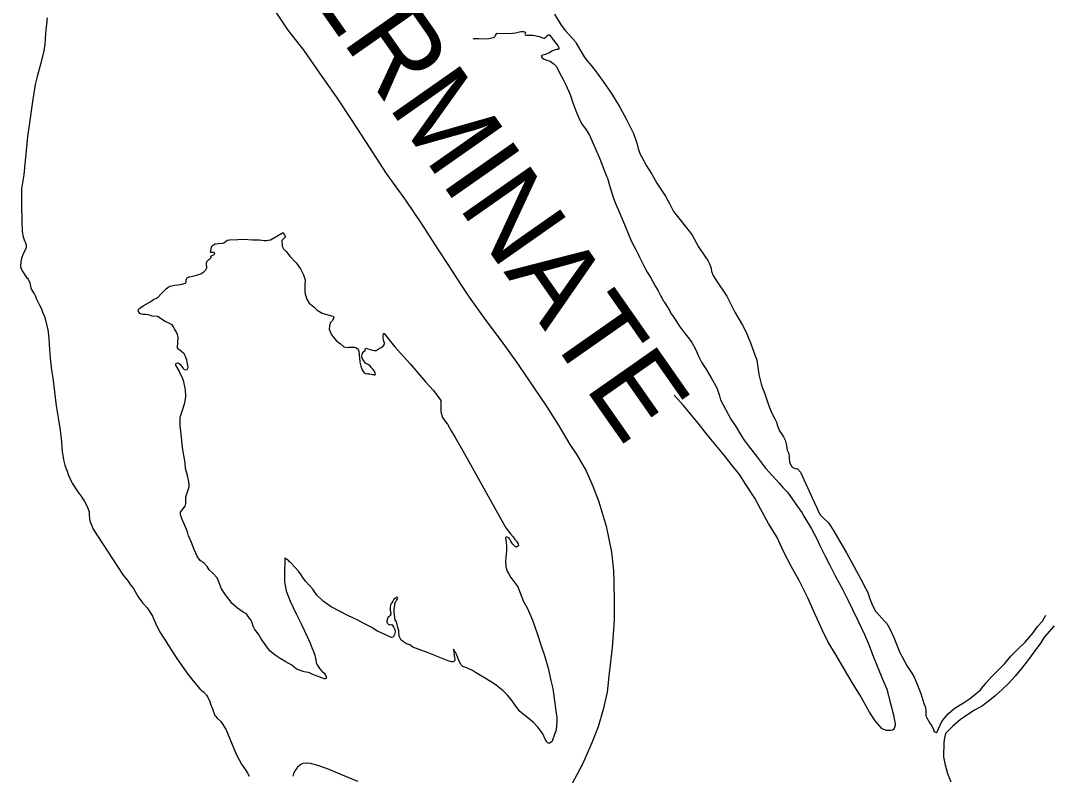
# Model space of a CAD drawing. Extents: x -117616 to 64730, y 54117 to 789866.
# Drawn here: x 62152 to 62218.2, y 55419.3 to 55467.6 of the extents above; entities that cross this region are included whole.
import ezdxf

# ---------------------------------------------------------------- set-up
doc = ezdxf.new("R2010")
doc.units = 0
doc.layers.add('3', color=7, linetype='Continuous')
doc.layers.add('9', color=7, linetype='Continuous')

msp = doc.modelspace()

# ---------------------------------------------------------------- linework, layer by layer
at = {"layer": '3'}
for points in [[(62167.221, 55469.914), (62169.146, 55467.026), (62170.158, 55465.72), (62171.155, 55464.273), (62172.226, 55462.748), (62173.278, 55461.172), (62174.343, 55459.546), (62175.44, 55457.841), (62176.668, 55456.141), (62177.687, 55454.634), (62178.711, 55453.027), (62179.456, 55451.891), (62180.181, 55450.764), (62180.743, 55449.943), (62181.823, 55448.438), (62182.805, 55447.141), (62183.875, 55445.626), (62184.872, 55444.188), (62185.722, 55442.926), (62186.49, 55441.71), (62187.187, 55440.512), (62187.643, 55439.857), (62188.244, 55438.826), (62188.664, 55437.837), (62189.021, 55436.897), (62189.271, 55436.143), (62189.515, 55435.279), (62189.688, 55434.452), (62189.861, 55433.615), (62189.977, 55432.454), (62190.018, 55431.652), (62190.026, 55430.457), (62190.023, 55429.271), (62189.911, 55427.528), (62189.707, 55425.883), (62189.584, 55424.672), (62189.328, 55423.557), (62189.002, 55422.449), (62188.593, 55421.428), (62187.997, 55420.048), (62186.777, 55417.77)], [(62173.609, 55418.938), (62172.642, 55419.361), (62171.787, 55419.72), (62171.25, 55419.909), (62170.915, 55420.017), (62170.592, 55420.094), (62170.321, 55420.124), (62170.102, 55420.095), (62169.964, 55420.039), (62169.761, 55419.861), (62169.6, 55419.653), (62169.498, 55419.448), (62169.454, 55419.286)]]:
    msp.add_lwpolyline(points, dxfattribs=at)
at = {"layer": '9'}
for points in [[(62186.218, 55468.042), (62186.646, 55467.346), (62186.911, 55466.974), (62187.193, 55466.674), (62187.549, 55466.266), (62187.592, 55466.198), (62187.838, 55465.785), (62188.117, 55465.314), (62188.213, 55465.157), (62188.579, 55464.74), (62188.875, 55464.359), (62189.319, 55463.734), (62189.86, 55462.972), (62190.395, 55462.089), (62190.825, 55461.312), (62191.271, 55460.405), (62191.405, 55460.049), (62191.508, 55459.721), (62191.569, 55459.453), (62191.682, 55459.135), (62191.779, 55458.938), (62192.103, 55458.348), (62192.434, 55457.809), (62192.767, 55457.239), (62193.31, 55456.397), (62193.579, 55455.935), (62193.839, 55455.413), (62194.998, 55453.942), (62195.429, 55453.155), (62195.885, 55452.5), (62196.034, 55452.275), (62196.153, 55452.038), (62196.234, 55451.77), (62196.272, 55451.571), (62196.371, 55451.323), (62196.533, 55451.038), (62197.233, 55450.011), (62197.764, 55448.987), (62198.247, 55448.152), (62198.453, 55447.749), (62198.752, 55447.017), (62198.953, 55446.482), (62199.156, 55445.908), (62199.25, 55445.308), (62199.292, 55444.999), (62199.436, 55444.392), (62199.504, 55444.183), (62199.659, 55443.808), (62199.932, 55442.984), (62200.065, 55442.658), (62200.229, 55442.293)], [(62153.722, 55467.814), (62153.622, 55466.815), (62153.569, 55466.12), (62153.525, 55465.706), (62153.327, 55464.915), (62153.08, 55464.061), (62152.96, 55463.554), (62152.76, 55462.3), (62152.607, 55461.099), (62152.463, 55460.209), (62152.24, 55457.759), (62152.094, 55456.879), (62152.077, 55455.793), (62152.106, 55454.81), (62152.123, 55454.137), (62152.186, 55453.798), (62152.254, 55453.6), (62152.298, 55453.501), (62152.341, 55453.412), (62152.364, 55453.353), (62152.387, 55453.284), (62152.392, 55453.143), (62152.357, 55453.031), (62152.199, 55452.703), (62152.091, 55452.408), (62152.038, 55452.225), (62152.031, 55451.893), (62152.067, 55451.754), (62152.175, 55451.557), (62152.399, 55451.204), (62152.461, 55451.157), (62152.503, 55451.088), (62152.612, 55450.861), (62152.685, 55450.532), (62152.741, 55450.384), (62152.806, 55450.276), (62152.858, 55450.218), (62152.921, 55450.14), (62152.976, 55450.011), (62153.032, 55449.853), (62153.217, 55449.478), (62153.359, 55449.193), (62153.427, 55448.984), (62153.548, 55448.698), (62153.761, 55447.862), (62153.833, 55447.313), (62153.86, 55446.882)], [(62180.997, 55466.46), (62181.069, 55466.483), (62181.339, 55466.483), (62181.93, 55466.476), (62182.207, 55466.538), (62182.317, 55466.552), (62182.356, 55466.564), (62182.395, 55466.605), (62182.413, 55466.646), (62182.441, 55466.708)], [(62182.441, 55466.708), (62182.46, 55466.728), (62182.498, 55466.78), (62182.546, 55466.822), (62183.057, 55466.802), (62183.516, 55466.82), (62183.705, 55466.858), (62183.883, 55466.905), (62184.062, 55466.932), (62184.131, 55466.945), (62184.232, 55466.939), (62184.313, 55466.912), (62184.344, 55466.873), (62184.327, 55466.802), (62184.319, 55466.762), (62184.33, 55466.722), (62184.391, 55466.704), (62184.641, 55466.694), (62184.821, 55466.701), (62185.033, 55466.669), (62185.255, 55466.608), (62185.387, 55466.553), (62185.468, 55466.526), (62185.529, 55466.518), (62185.589, 55466.52), (62185.598, 55466.531), (62185.676, 55466.574), (62185.743, 55466.667), (62185.791, 55466.709), (62185.801, 55466.72), (62185.89, 55466.733), (62186.05, 55466.488), (62186.376, 55466.089), (62186.439, 55466.001), (62186.484, 55465.883), (62186.487, 55465.812), (62186.447, 55465.801), (62186.418, 55465.79), (62186.328, 55465.776), (62186.219, 55465.752), (62186.081, 55465.706), (62185.857, 55465.556), (62185.768, 55465.523), (62185.63, 55465.467), (62185.551, 55465.454), (62185.452, 55465.42), (62185.403, 55465.398), (62185.355, 55465.356), (62185.419, 55465.248), (62185.542, 55465.162), (62185.715, 55465.099), (62185.937, 55465.037), (62186.185, 55464.846), (62186.341, 55464.691), (62186.537, 55464.287), (62186.742, 55463.914), (62186.937, 55463.529), (62187.212, 55462.897), (62187.373, 55462.381), (62187.627, 55461.758), (62187.858, 55461.225), (62187.978, 55460.989), (62188.199, 55460.716), (62188.423, 55460.353), (62188.84, 55459.425), (62189.105, 55458.783), (62189.283, 55458.337), (62189.549, 55457.675), (62189.594, 55457.546), (62189.755, 55457.02), (62189.917, 55456.454), (62190.074, 55456.028), (62190.415, 55455.258), (62190.57, 55454.882), (62190.681, 55454.595), (62190.968, 55453.913), (62191.166, 55453.459), (62191.425, 55452.977), (62191.557, 55452.69), (62191.654, 55452.493), (62191.937, 55451.932), (62192.153, 55451.528), (62192.367, 55451.175), (62192.678, 55450.625), (62192.85, 55450.34), (62193.023, 55450.006), (62193.056, 55449.927)], [(62162.142, 55446.606), (62162.069, 55446.693), (62162.104, 55447.066), (62162.123, 55447.349), (62162.075, 55447.558), (62161.999, 55447.705), (62161.881, 55447.912), (62161.794, 55448.069), (62161.721, 55448.157), (62161.435, 55448.316), (62161.292, 55448.371), (62160.79, 55448.692), (62160.458, 55448.72), (62160.337, 55448.755), (62160.185, 55448.799), (62160.014, 55448.833), (62159.864, 55448.837), (62159.743, 55448.842), (62159.651, 55448.899), (62159.555, 55449.056), (62159.581, 55449.147), (62159.668, 55449.241), (62159.872, 55449.39), (62160.361, 55449.67), (62160.546, 55449.798), (62160.811, 55449.909), (62161.012, 55450.138), (62161.244, 55450.358), (62161.35, 55450.463), (62161.485, 55450.569), (62161.593, 55450.643), (62161.91, 55450.696), (62162.099, 55450.723), (62162.347, 55450.773), (62162.585, 55450.833), (62162.632, 55450.915), (62162.628, 55451.016), (62162.655, 55451.097), (62162.692, 55451.179), (62162.809, 55451.244), (62163.058, 55451.274), (62163.365, 55451.356), (62163.562, 55451.424), (62163.757, 55451.552), (62163.882, 55451.678), (62163.946, 55451.821), (62163.954, 55451.892), (62163.919, 55452.011), (62163.924, 55452.132), (62163.98, 55452.234), (62164.085, 55452.349), (62164.134, 55452.391), (62164.192, 55452.434), (62164.221, 55452.465), (62164.217, 55452.565), (62164.452, 55452.695), (62164.418, 55452.804), (62164.188, 55452.795), (62164.204, 55452.896), (62164.219, 55453.007), (62164.255, 55453.129), (62164.302, 55453.202), (62164.369, 55453.285), (62164.476, 55453.359), (62164.944, 55453.398), (62165.043, 55453.422), (62165.257, 55453.581), (62165.406, 55453.607), (62165.935, 55453.638), (62166.324, 55453.653), (62166.886, 55453.605), (62167.326, 55453.602), (62167.618, 55453.554), (62167.768, 55453.559), (62167.847, 55453.583), (62167.907, 55453.595), (62168.026, 55453.61), (62168.838, 55454.074), (62168.989, 55453.799), (62168.748, 55453.568), (62168.753, 55453.448), (62168.766, 55453.378), (62168.782, 55453.208), (62168.849, 55453.039), (62169.026, 55452.856), (62169.268, 55452.554), (62169.675, 55452.138), (62169.95, 55451.757), (62170.145, 55451.363), (62170.238, 55451.055), (62170.23, 55450.753), (62170.216, 55450.602), (62170.217, 55450.311), (62170.244, 55450.131), (62170.357, 55449.814), (62170.507, 55449.548), (62170.828, 55449.29), (62171.025, 55449.107), (62171.343, 55448.908), (62171.545, 55448.846), (62171.778, 55448.775)], [(62193.228, 55449.632), (62193.056, 55449.927)], [(62193.228, 55449.632), (62193.399, 55449.357), (62193.591, 55449.053), (62193.645, 55448.945), (62193.815, 55448.701), (62194.017, 55448.387), (62194.188, 55448.103), (62194.642, 55447.508), (62194.779, 55447.342), (62195.011, 55447.04), (62195.206, 55446.656), (62195.447, 55446.123), (62195.63, 55445.788), (62195.94, 55445.278), (62196.25, 55444.778), (62196.596, 55444.139), (62196.766, 55443.633), (62196.836, 55443.365), (62197.495, 55442.125), (62197.824, 55441.655), (62198.166, 55441.096), (62198.358, 55440.792), (62198.675, 55440.363), (62198.928, 55440.031), (62199.213, 55439.671), (62199.656, 55439.075), (62199.74, 55438.978), (62200.148, 55438.532), (62200.588, 55438.037), (62200.828, 55437.765), (62201.121, 55437.455), (62201.777, 55436.537), (62202.052, 55436.166), (62202.182, 55435.92), (62202.664, 55435.115), (62202.999, 55434.465), (62203.196, 55434.041), (62203.543, 55433.361), (62203.836, 55432.79), (62204.183, 55432.101), (62204.647, 55431.245), (62205.005, 55430.536), (62205.288, 55429.944), (62205.669, 55429.166), (62206.062, 55428.347), (62206.305, 55427.754), (62206.617, 55426.962), (62206.883, 55426.29), (62207.215, 55425.499), (62207.48, 55424.857), (62207.596, 55424.459), (62207.68, 55424.091), (62207.809, 55423.624), (62207.857, 55423.425), (62207.929, 55423.126), (62207.941, 55423.066), (62208.028, 55422.638), (62208.022, 55422.527), (62207.96, 55422.334), (62207.912, 55422.282), (62207.854, 55422.239), (62207.745, 55422.205), (62207.475, 55422.214), (62207.18, 55422.323), (62206.75, 55422.838), (62206.388, 55423.377), (62205.754, 55424.487), (62205.273, 55425.282), (62204.78, 55426.106), (62204.233, 55427.039), (62203.741, 55427.854), (62203.371, 55428.613), (62202.803, 55429.826), (62202.428, 55430.705), (62201.865, 55431.798), (62201.39, 55432.674), (62200.892, 55433.618), (62200.465, 55434.556), (62199.92, 55435.449), (62199.392, 55436.392), (62199.036, 55437.072), (62198.451, 55437.953), (62198.056, 55438.58), (62197.529, 55439.243), (62197.077, 55439.817), (62196.331, 55440.722), (62196.225, 55440.859), (62195.848, 55441.306), (62195.415, 55441.872), (62194.984, 55442.397), (62194.47, 55443), (62193.861, 55443.674)], [(62171.778, 55448.775), (62171.909, 55448.75), (62172.03, 55448.724), (62172.052, 55448.685), (62172.074, 55448.616), (62171.982, 55448.431), (62171.877, 55448.306), (62171.794, 55448.112), (62171.783, 55447.891), (62171.938, 55447.525), (62172.032, 55447.408), (62172.232, 55447.155), (62172.511, 55446.945), (62172.728, 55446.763), (62172.859, 55446.738), (62172.999, 55446.723), (62173.049, 55446.735), (62173.329, 55446.736), (62173.409, 55446.739), (62173.5, 55446.713), (62173.634, 55446.608), (62173.68, 55446.469), (62173.726, 55446.059), (62173.747, 55445.768), (62173.807, 55445.519), (62173.874, 55445.341), (62173.918, 55445.242), (62174.034, 55445.106), (62174.115, 55445.059), (62174.176, 55445.052), (62174.276, 55445.036), (62174.377, 55445.029), (62174.467, 55445.013), (62174.558, 55444.996), (62174.618, 55444.989), (62174.659, 55444.97), (62174.699, 55444.962), (62174.739, 55444.983), (62174.725, 55445.073), (62174.69, 55445.203), (62174.596, 55445.309), (62174.501, 55445.426), (62174.407, 55445.533), (62174.334, 55445.59), (62174.232, 55445.647), (62174.14, 55445.693), (62174.057, 55445.78), (62173.994, 55445.858), (62173.897, 55446.025), (62173.886, 55446.065), (62173.881, 55446.175), (62173.887, 55446.276), (62173.896, 55446.296), (62173.942, 55446.409), (62173.981, 55446.43), (62174.058, 55446.504), (62174.103, 55446.626), (62174.152, 55446.668), (62174.264, 55446.622), (62174.557, 55446.544), (62174.657, 55446.527), (62174.797, 55446.533), (62174.856, 55446.575), (62174.993, 55446.651), (62175.11, 55446.716), (62175.246, 55446.812), (62175.323, 55446.905), (62175.312, 55446.915), (62175.329, 55446.996), (62175.284, 55447.115), (62175.26, 55447.224), (62175.246, 55447.324), (62175.235, 55447.344), (62175.23, 55447.474), (62175.265, 55447.606), (62175.294, 55447.618), (62175.958, 55446.77), (62176.962, 55445.674), (62177.948, 55444.517), (62178.47, 55443.955)], [(62153.86, 55446.882), (62153.924, 55446.03), (62154.014, 55445.26), (62154.084, 55444.76), (62154.199, 55443.881), (62154.304, 55442.981), (62154.46, 55442.083), (62154.566, 55441.434), (62154.628, 55440.874), (62154.645, 55440.684), (62154.689, 55440.072), (62154.771, 55439.533), (62154.795, 55439.434), (62154.865, 55439.185), (62154.944, 55438.947), (62155, 55438.799), (62155.068, 55438.6), (62155.277, 55438.126), (62155.32, 55438.038), (62155.692, 55437.49), (62155.956, 55437.138), (62156.117, 55436.854), (62156.299, 55436.549), (62156.39, 55436.272), (62156.413, 55436.202), (62156.42, 55436.032), (62156.441, 55435.731), (62156.466, 55435.621), (62156.677, 55435.097), (62158.231, 55432.707), (62158.604, 55432.139), (62158.909, 55431.759), (62159.047, 55431.554), (62159.248, 55431.291), (62159.558, 55430.77), (62159.791, 55430.448), (62159.845, 55430.35), (62160.137, 55430.05), (62160.297, 55429.805), (62160.468, 55429.52), (62160.721, 55428.938), (62160.807, 55428.78), (62160.926, 55428.544), (62161.246, 55428.054), (62161.492, 55427.642), (62161.641, 55427.417), (62161.982, 55426.888), (62162.322, 55426.399), (62162.661, 55425.9), (62163.061, 55425.413), (62163.512, 55424.868), (62163.523, 55424.859), (62163.74, 55424.676), (62163.928, 55424.463), (62164.002, 55424.365), (62164.122, 55424.129), (62164.213, 55423.841), (62164.303, 55423.593), (62164.47, 55423.168), (62164.502, 55423.119), (62164.606, 55423.003), (62164.855, 55422.791), (62165.174, 55422.302), (62165.828, 55420.7), (62166.163, 55420.06), (62166.46, 55419.63), (62166.524, 55419.532), (62166.654, 55419.286)], [(62170.789, 55427.266), (62170.858, 55427.037), (62170.893, 55426.898), (62170.919, 55426.748), (62170.957, 55426.539), (62171.012, 55426.42), (62171.098, 55426.283), (62171.171, 55426.186), (62171.308, 55426.01), (62171.443, 55425.895), (62171.527, 55425.788), (62171.593, 55425.65), (62171.615, 55425.58), (62171.558, 55425.508), (62171.478, 55425.514), (62171.153, 55425.642), (62170.778, 55425.768), (62170.522, 55425.909), (62170.442, 55425.916), (62170.19, 55425.966), (62169.693, 55426.137), (62169.383, 55426.396), (62169.015, 55426.603), (62168.646, 55426.819), (62168.327, 55427.038), (62167.986, 55427.316), (62167.744, 55427.628), (62167.436, 55428.067), (62167.264, 55428.382), (62167.032, 55428.674), (62166.914, 55428.891), (62166.846, 55429.099), (62166.758, 55429.287), (62166.59, 55429.501), (62166.483, 55429.667), (62166.278, 55429.79), (62165.908, 55430.037), (62165.577, 55430.325), (62165.155, 55430.881), (62164.899, 55431.283), (62164.744, 55431.658), (62164.611, 55431.985), (62164.339, 55432.275), (62164.101, 55432.487), (62163.963, 55432.693), (62163.784, 55432.917), (62163.517, 55433.097), (62163.358, 55433.322), (62163.129, 55433.795), (62162.972, 55434.241), (62162.785, 55434.655), (62162.714, 55434.924), (62162.538, 55435.329), (62162.373, 55435.714), (62162.272, 55436.001), (62162.275, 55436.172), (62162.417, 55436.369), (62162.56, 55436.555), (62162.613, 55436.728), (62162.605, 55436.939), (62162.607, 55437.14), (62162.668, 55437.353), (62162.731, 55437.547), (62162.811, 55437.801), (62162.825, 55437.932), (62162.798, 55438.122), (62162.702, 55438.53), (62162.584, 55438.978), (62162.56, 55439.338), (62162.505, 55439.708), (62162.442, 55440.037), (62162.374, 55440.486), (62162.335, 55440.977), (62162.235, 55441.727), (62162.235, 55442.249), (62162.414, 55442.779), (62162.548, 55443.186), (62162.612, 55443.58), (62162.575, 55444.011), (62162.485, 55444.51), (62162.395, 55444.777), (62162.243, 55445.063), (62162.187, 55445.221), (62161.973, 55445.584), (62161.96, 55445.664), (62162.017, 55445.717), (62162.107, 55445.74), (62162.23, 55445.645), (62162.346, 55445.499), (62162.431, 55445.371), (62162.483, 55445.323), (62162.575, 55445.287), (62162.615, 55445.278), (62162.684, 55445.311), (62162.759, 55445.435), (62162.743, 55445.575), (62162.67, 55445.913), (62162.591, 55446.141), (62162.494, 55446.318), (62162.359, 55446.444), (62162.142, 55446.606)], [(62178.47, 55443.955), (62178.935, 55443.321)], [(62178.935, 55443.321), (62178.929, 55442.979), (62178.933, 55442.617), (62178.957, 55442.508), (62179.048, 55442.24), (62179.187, 55442.014), (62179.239, 55441.956), (62179.364, 55441.821), (62179.472, 55441.624), (62179.602, 55441.378), (62179.837, 55441.005), (62180.311, 55440.15), (62183.097, 55435.186), (62183.403, 55434.786), (62183.571, 55434.602), (62183.677, 55434.436), (62183.772, 55434.319), (62183.878, 55434.162), (62183.914, 55434.023), (62183.777, 55433.937), (62183.695, 55433.974), (62183.549, 55434.129), (62183.485, 55434.227), (62183.412, 55434.325), (62183.347, 55434.453), (62183.283, 55434.541), (62183.181, 55434.587), (62183.102, 55434.574), (62183.065, 55434.492), (62183.114, 55434.253), (62183.144, 55434.003), (62183.146, 55433.711), (62183.094, 55433.247), (62183.073, 55433.035), (62183.086, 55432.684), (62183.178, 55432.396), (62183.338, 55432.142), (62183.423, 55432.004), (62183.857, 55431.399), (62183.968, 55431.132), (62184.234, 55430.469), (62184.482, 55430.017), (62184.792, 55429.265), (62185.073, 55428.483), (62185.369, 55427.57), (62185.561, 55427.015), (62185.794, 55426.19), (62185.984, 55425.414), (62186.095, 55424.886), (62186.181, 55424.246), (62186.222, 55423.957), (62186.293, 55423.437), (62186.368, 55423.038), (62186.368, 55422.797), (62186.32, 55422.243), (62186.194, 55421.896), (62186.085, 55421.6), (62186.077, 55421.55), (62186.02, 55421.477), (62185.932, 55421.424), (62185.864, 55421.381), (62185.782, 55421.418), (62185.71, 55421.475), (62185.603, 55421.652), (62185.46, 55421.988), (62185.154, 55422.397), (62184.871, 55422.728), (62184.499, 55423.025), (62183.993, 55423.417), (62183.687, 55423.826), (62183.442, 55424.189), (62183.192, 55424.46), (62182.92, 55424.751), (62182.487, 55425.085), (62182.281, 55425.238), (62181.83, 55425.511), (62181.472, 55425.718), (62181.154, 55425.917), (62180.959, 55426.04), (62180.684, 55426.169), (62180.47, 55426.251), (62180.338, 55426.306), (62180.234, 55426.403), (62180.062, 55426.728), (62180.004, 55426.926), (62179.938, 55427.074), (62179.905, 55427.153), (62179.842, 55427.231), (62179.787, 55427.34), (62179.734, 55427.418), (62179.763, 55427.198), (62179.778, 55427.068), (62179.782, 55426.978), (62179.806, 55426.878), (62179.819, 55426.788), (62179.823, 55426.688), (62179.766, 55426.615), (62179.727, 55426.594), (62179.606, 55426.609), (62179.404, 55426.661), (62178.123, 55427.183)], [(62200.229, 55442.293), (62200.315, 55442.146), (62200.434, 55441.929), (62200.492, 55441.711), (62200.625, 55441.394), (62200.861, 55440.992), (62200.979, 55440.785), (62201.062, 55440.447), (62201.115, 55440.138), (62201.191, 55439.97), (62201.204, 55439.91), (62201.232, 55439.7), (62201.265, 55439.36), (62201.375, 55439.123), (62201.478, 55439.047), (62201.62, 55438.982), (62201.762, 55438.948), (62201.95, 55438.744), (62202.627, 55437.294), (62202.693, 55437.146), (62203.022, 55436.415), (62203.077, 55436.287), (62203.249, 55435.982), (62203.353, 55435.886), (62203.779, 55435.481), (62204.09, 55434.96), (62204.476, 55434.313), (62204.895, 55433.576), (62205.4, 55432.691), (62205.832, 55431.885), (62206.124, 55431.313), (62206.265, 55431.048), (62206.401, 55430.631), (62206.568, 55430.206), (62206.752, 55429.851), (62206.982, 55429.609), (62207.369, 55429.192), (62207.484, 55429.056), (62207.666, 55428.762), (62207.939, 55428.16), (62208.317, 55427.21), (62208.782, 55426.335), (62209.09, 55425.875), (62209.23, 55425.619), (62209.362, 55425.323), (62209.662, 55424.571), (62209.857, 55423.936), (62209.945, 55423.738), (62209.993, 55423.519), (62209.98, 55423.358), (62209.978, 55423.157), (62210.044, 55423.009), (62210.236, 55422.685), (62210.3, 55422.587), (62210.364, 55422.489), (62210.46, 55422.332), (62210.496, 55422.183), (62210.538, 55422.134), (62210.641, 55422.078), (62210.708, 55422.131), (62210.783, 55422.274), (62211.013, 55422.776), (62211.155, 55422.982), (62211.413, 55423.274), (62211.751, 55423.579), (62211.897, 55423.685), (62212.083, 55423.783), (62212.396, 55423.976), (62212.786, 55424.232), (62213.193, 55424.55), (62213.483, 55424.812), (62213.855, 55425.269), (62214.19, 55425.634), (62214.642, 55426.094), (62215.046, 55426.502), (62215.428, 55426.969), (62215.851, 55427.397), (62216.353, 55427.859), (62216.849, 55428.452), (62217.143, 55428.865), (62217.46, 55429.209), (62217.665, 55429.579)], [(62178.123, 55427.183), (62177.545, 55427.392), (62177.139, 55427.546), (62176.953, 55427.68), (62176.74, 55427.762), (62176.535, 55427.884), (62176.494, 55427.923), (62176.391, 55427.989), (62176.348, 55428.068), (62176.293, 55428.196), (62176.244, 55428.425), (62176.247, 55428.586), (62176.169, 55428.804), (62176.156, 55428.884), (62176.118, 55429.083), (62176.094, 55429.173), (62176.019, 55429.291), (62175.997, 55429.35), (62175.985, 55429.41), (62175.949, 55429.81), (62175.943, 55429.971), (62175.983, 55430.213), (62175.997, 55430.375), (62176.025, 55430.406), (62176.101, 55430.52), (62176.138, 55430.581), (62176.166, 55430.653), (62176.164, 55430.683), (62176.153, 55430.722), (62176.123, 55430.721), (62176.103, 55430.721), (62176.025, 55430.677), (62175.927, 55430.613), (62175.852, 55430.49), (62175.796, 55430.387), (62175.739, 55430.304), (62175.703, 55430.202), (62175.687, 55430.121), (62175.691, 55430.001), (62175.694, 55429.931), (62175.72, 55429.791), (62175.722, 55429.721), (62175.725, 55429.661), (62175.66, 55429.538), (62175.602, 55429.485), (62175.544, 55429.433), (62175.499, 55429.3), (62175.482, 55429.219), (62175.474, 55429.169), (62175.497, 55429.109), (62175.529, 55429.05), (62175.57, 55429.022), (62175.632, 55428.984), (62175.672, 55428.975), (62175.771, 55428.989), (62175.822, 55428.961), (62175.855, 55428.902), (62175.919, 55428.794), (62175.984, 55428.676), (62176.01, 55428.527), (62175.993, 55428.436), (62175.967, 55428.344), (62175.911, 55428.231), (62175.853, 55428.179), (62175.784, 55428.166), (62175.591, 55428.249), (62175.163, 55428.433), (62174.837, 55428.591), (62174.468, 55428.827), (62174.049, 55429.042), (62173.61, 55429.276), (62172.988, 55429.573), (62172.447, 55429.843), (62171.916, 55430.123), (62171.391, 55430.494), (62170.997, 55430.86), (62170.731, 55431.262), (62170.261, 55431.766), (62170.102, 55431.991), (62169.984, 55432.177), (62169.825, 55432.402), (62169.345, 55432.915), (62169.251, 55433.012), (62169.209, 55433.06), (62169.147, 55433.108), (62169.055, 55433.165), (62168.993, 55433.223), (62168.952, 55433.241), (62168.946, 55433.14), (62168.937, 55432.869), (62168.931, 55432.507), (62168.914, 55432.185), (62168.922, 55431.713), (62169.025, 55431.154), (62169.281, 55430.481), (62169.663, 55429.673), (62170.011, 55428.983), (62170.381, 55428.224), (62170.558, 55427.789), (62170.701, 55427.453), (62170.789, 55427.266)], [(62218.211, 55428.917), (62217.59, 55428.2), (62217.335, 55427.798), (62216.955, 55427.31), (62216.738, 55426.98), (62216.49, 55426.659), (62216.099, 55426.172), (62215.699, 55425.684), (62215.267, 55425.224), (62214.882, 55424.837), (62214.418, 55424.437), (62214.079, 55424.153), (62213.604, 55423.782), (62213.095, 55423.501), (62212.792, 55423.308), (62212.451, 55423.074), (62212.208, 55422.903), (62211.704, 55422.492), (62211.474, 55422.241), (62211.253, 55422.012), (62211.174, 55421.747), (62211.146, 55421.435), (62211.122, 55420.52), (62211.199, 55420.101), (62211.364, 55419.464), (62211.575, 55418.93)]]:
    msp.add_lwpolyline(points, dxfattribs=at)

# ---------------------------------------------------------------- texts
at = {"layer": '3'}
msp.add_text('INDETERMINATE', height=5.27999, rotation=305, dxfattribs=at).set_placement((62157.727, 55487.553))

doc.saveas('drawing.dxf')
